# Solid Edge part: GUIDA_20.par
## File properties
Subject: GUIDA_20
Author: Francesco
Template: Normal.par
Last saved by: Francesco
Revision: 6
Application: Solid Edge
Densità: 7833,000 kg/m^3
Precisione: 0,990
Tipo di contenuto documento: 0
Document Number: KR0133
Material: Acciaio
Stile della faccia: Acciaio
Stile di riempimento: ANSI32(Acciaio)
Stile virtuale: Acciaio lavorato a macchina
Coef. of Thermal Exp: 0.0
Thermal Conductivity: 32.0
Specific Heat: 481.0
Modulus of Elasticity: 199947953000.0
Poisson's Ratio: 0.29
Yield Stress: 262000766.0
Ultimate Stress: 358527364.0
Elongation: 0.0
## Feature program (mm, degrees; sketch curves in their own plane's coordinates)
sketch for "unnamed Protrusion 1" plane through (0, 0, 0) normal (0, -1, 0) x-axis (1, 0, 0)
  line (46.8881, 0) -> (46.8881, 5)
  line (33.7167, 5) -> (46.8881, 5)
  line (33.7167, 5) -> (33.7167, 8.7)
  line (33.7167, 8.7) -> (31.4167, 8.7)
  line (31.4167, 8.7) -> (28.2861, 17.791)
  line (24.3881, 37) -> (24.3881, 0)
  line (46.8881, 0) -> (24.3881, 0)
  dimension (linear) = 46.8881
  dimension (linear) = 24.3881
extrude "unnamed Protrusion 1" add finite 700 along -normal
sketch for "unnamed Cutout 1" plane through (35.6381, 0, 18.5) normal (0, -1, 0) x-axis (1, 0, 0)
  line (-11.25, -18.5) -> (-6.35, -18.5)
  line (-6.35, -18.5) -> (-6.35, -12.5)
  line (-6.35, -12.5) -> (-9.35, -12.5)
  line (-9.35, -12.5) -> (-9.35, -9.5)
  line (-9.35, -9.5) -> (-11.25, -9.5)
  line (-11.25, -9.5) -> (-11.25, -18.5)
  dimension (linear) = 6.35
  dimension (linear) = 9.35
extrude "unnamed Cutout 1" cut to key point along -normal
fillet "Rotondo_1" radius 3
fillet "Rotondo_2" radius 1
sketch for "Foro_1" plane through (39.8024, 350, 5) normal (0, 0, 1) x-axis (0, 1, 0)
  hole centre (-150, 0.5893) bore radius 2.675
hole "Foro_1" diameter 5.35 through
sketch for "unnamed Hole 1" plane through (39.8024, 350, 5) normal (0, 0, 1) x-axis (0, 1, 0)
  hole centre (0, 0.5893) bore radius 2.675
hole "unnamed Hole 1" through
sketch for "unnamed Hole 2" plane through (39.8024, 350, 5) normal (0, 0, 1) x-axis (0, 1, 0)
  hole centre (150, 0.5893) bore radius 2.675
hole "unnamed Hole 2" through
sketch for "unnamed Hole 3" plane through (39.8024, 350, 5) normal (0, 0, 1) x-axis (0, 1, 0)
  hole centre (300, 0.5893) bore radius 2.675
hole "unnamed Hole 3" through
sketch for "unnamed Hole 4" plane through (39.8024, 350, 5) normal (0, 0, 1) x-axis (0, 1, 0)
  hole centre (-300, 0.5893) bore radius 2.675
hole "unnamed Hole 4" through
pattern "unnamed Pattern 1" of "Foro_1", "unnamed Hole 1", "unnamed Hole 2", "unnamed Hole 3", "unnamed Hole 4"
body pattern "unnamed BodyPattern 1"
pattern "unnamed Pattern 2"
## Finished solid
Body 1: solid body, 38 faces, 98 edges, 52 vertices.
  Faces by surface: plane 21, cylinder 17
  Edges by curve: line 64, circle 34
Bounding box of the edges (mm): 45.000 x 700.000 x 37.000, from (1.8881, 0, 0) to (46.8881, 700, 37).
Cylindrical faces by radius (mm): R1 x4, R2.675 x10, R3 x2, R10 x1
Planar faces by outward normal: +x 4, +y 1, +z 4, -x 4, -y 1, -z 5, oblique 2
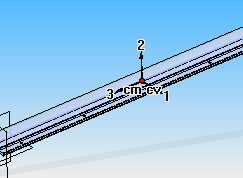
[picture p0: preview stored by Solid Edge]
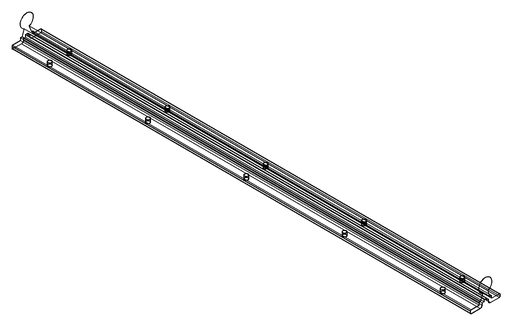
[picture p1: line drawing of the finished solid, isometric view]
